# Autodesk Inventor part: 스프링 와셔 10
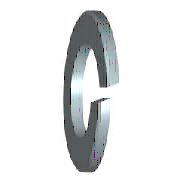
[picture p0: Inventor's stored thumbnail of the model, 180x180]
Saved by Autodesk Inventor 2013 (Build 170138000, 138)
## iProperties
Created: 2012-02
Part Number: 스프링 와셔 10
Material: 강철, 연강
Description: 스프링 잠금 와셔
Document SubType Name: Modeling
Standard: KS B 1324
Designer: mduedu
Standards Organization: KS
Language: ko-KR
Size Designation: 번호 2 - 10
Categories: <MemberInstance><Categories><Category DisplayName="조임쇠" InternalName="e4da775c-781d-43d5-af7c-5136215cf5a6" Mnemonic="FSTN"><Category DisplayName="와셔" InternalN
Density: 1 g/cm^3
IsCustomPart: 1
Author: mduedu
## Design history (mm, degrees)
sketch "스케치1"
  geometry: C1 r 8.8 at (0, 0); C2 r 5.1 at (0, 0); 1 further point
  constraints: 2 centre point, 2 coincident
  dimensions: "d0" = 10.2 diameter of C2 (= SD1); "d1" = 17.6 diameter of C1 (= SD2)
extrude "본체" new body sketch "스케치1" distance "d2" = 2.5 (= SD); taper "d3" = 0 deg
sketch "스케치2"
  geometry: L1 (0, -5.1)-(0, 5.1) reference; L2 (2.5, 8.8)-(2.5, -8.8) reference; L3 (-1.2, 0)-(7.2, 0) reference; L4 (0, -0.5)-(2.5, 0.41); L5 (0, 0.5)-(2.5, 1.41)
  constraints: 4 end point, 4 point on line, 1 parallel
  dimensions: "d4" = 0.5 distance from line of L3 L4.start (= 0.2 x SD); "d5" = 0.5 distance from line of L3 L5.start (= 0.2 x SD); "d6" = 70 deg angle of L2 L4 (= FAWI)
extrude "절단부" cut sketch "스케치2" stored distance "d7" = 2.5 (= SD); taper "d8" = 0 deg
workaxis "Work Axis1"
workplane "Work Plane1"
body "Solid1"
other parameters: "SD1" = 10.2 [user parameter; used in 1 equation term], "SD2" = 17.6 [user parameter; used in 1 equation term], "SD" = 2.5 [user parameter; used in 4 equation terms], "FAWI" = 70 deg [user parameter; used in 1 equation term], "d9" = 0, "d10" = 0, "d11" = 0, "d12" = 0, "SDI" = 3.7 [user parameter]
